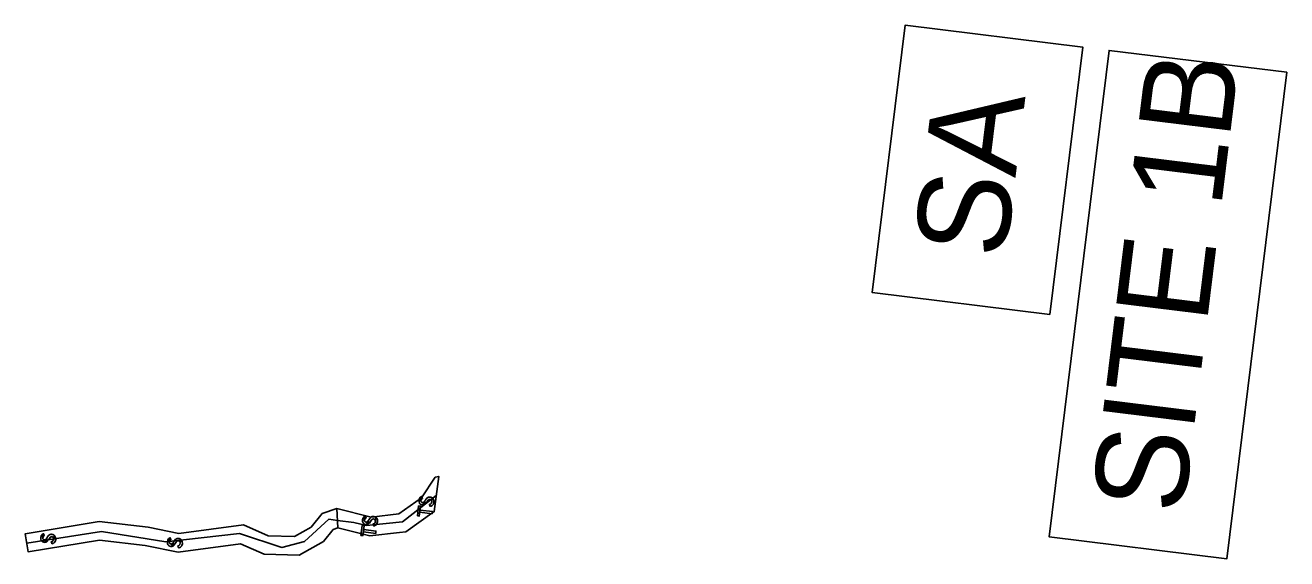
# Model space of a CAD drawing. Extents: x 474218 to 481634, y 484357 to 504997.
# Drawn here: x 481212.5 to 481417.5, y 489416.6 to 489503.2 of the extents above; entities that cross this region are included whole.
import ezdxf

# ---------------------------------------------------------------- set-up
doc = ezdxf.new("R2010")
doc.units = 0
for name, color, linetype in [('Exist Hydro Jurisdictional Stream or Body of Water', 7, 'Continuous'), ('Old_Level_29', 7, 'Continuous'), ('Prop Earthen Structure Impacts In Surface Waters Hatching CELL', 7, 'Continuous'), ('Prop Grid Mask', 7, 'Continuous'), ('Scratch_Level_4', 7, 'Continuous'), ('Temp Earthen Structure Impacts In Surface Waters Hatching CELL', 7, 'Continuous')]:
    doc.layers.add(name, color=color, linetype=linetype)

msp = doc.modelspace()

# ---------------------------------------------------------------- linework, layer by layer
at = {"layer": 'Exist Hydro Jurisdictional Stream or Body of Water'}
msp.add_lwpolyline([(481350.11, 489459.8), (481355.45, 489503.2), (481384.32, 489499.65), (481378.97, 489456.25)], close=True, dxfattribs=at)
at = {"layer": 'Old_Level_29'}
msp.add_lwpolyline([(481378.87, 489420.15), (481388.59, 489499.12), (481417.47, 489495.57), (481407.74, 489416.6)], close=True, dxfattribs=at)
at = {"layer": 'Prop Earthen Structure Impacts In Surface Waters Hatching CELL'}
msp.add_lwpolyline([(481263.15, 489424.75), (481260.77, 489423.93), (481258.97, 489421.73), (481256.27, 489420.19), (481251.99, 489420.32), (481247.94, 489422.08), (481237.44, 489420.72), (481232.46, 489421.72), (481224.51, 489422.64), (481212.5, 489420.66), (481212.99, 489417.7), (481224.59, 489419.61), (481231.98, 489418.76), (481237.33, 489417.69), (481247.5, 489419), (481251.33, 489417.34), (481257.02, 489417.17), (481260.94, 489419.4), (481262.55, 489421.37), (481263.29, 489421.62), (481263.15, 489424.75)], dxfattribs=at)
for points in [[(481215.03, 489419.78), (481215.03, 489419.75), (481215.1, 489420.33), (481215.1, 489420.32), (481215.02, 489420.04), (481215.02, 489420.04)], [(481215.64, 489419.27), (481215.73, 489419.26), (481215.78, 489419.7), (481215.69, 489419.66), (481215.56, 489419.67), (481215.55, 489419.67), (481215.52, 489419.69), (481215.44, 489419.73), (481215.42, 489419.77), (481215.38, 489419.82), (481215.37, 489419.84), (481215.37, 489419.86), (481215.36, 489419.92), (481215.35, 489420), (481215.43, 489420.64), (481215.39, 489420.63), (481215.26, 489420.54), (481215.23, 489420.52), (481215.1, 489420.33), (481215.03, 489419.75), (481215.11, 489419.57), (481215.13, 489419.52), (481215.24, 489419.42), (481215.27, 489419.39), (481215.29, 489419.37), (481215.31, 489419.36), (481215.31, 489419.35), (481215.33, 489419.35), (481215.37, 489419.33), (481215.39, 489419.32), (481215.47, 489419.29), (481215.5, 489419.28), (481215.51, 489419.27)], [(481215.51, 489420.29), (481215.6, 489420.35), (481215.54, 489420.52), (481215.52, 489420.58), (481215.49, 489420.66), (481215.47, 489420.66), (481215.46, 489420.65), (481215.45, 489420.65), (481215.43, 489420.64), (481215.35, 489420), (481215.39, 489420.16), (481215.41, 489420.18), (481215.41, 489420.19), (481215.43, 489420.21), (481215.48, 489420.27)], [(481215.88, 489419.31), (481215.93, 489419.33), (481216.01, 489419.95), (481215.94, 489419.85), (481215.83, 489419.72), (481215.78, 489419.7), (481215.73, 489419.26), (481215.77, 489419.28)], [(481217.1, 489419.92), (481217.11, 489419.77), (481217.19, 489420.42), (481217.17, 489420.44), (481217.17, 489420.44), (481217.16, 489420.45), (481217.12, 489420.48), (481217.1, 489420.49), (481217.09, 489420.49), (481217.02, 489420.52), (481216.99, 489420.53), (481216.97, 489420.53), (481216.88, 489420.56), (481216.83, 489420.56), (481216.69, 489420.57), (481216.64, 489420.57), (481216.59, 489420.55), (481216.49, 489420.51), (481216.49, 489420.51), (481216.42, 489420.48), (481216.36, 489420.42), (481216.23, 489420.29), (481216.2, 489420.25), (481216.07, 489420.05), (481216.01, 489419.95), (481215.93, 489419.33), (481215.99, 489419.37), (481216.11, 489419.47), (481216.14, 489419.51), (481216.27, 489419.68), (481216.33, 489419.77), (481216.42, 489419.91), (481216.53, 489420.07), (481216.58, 489420.11), (481216.64, 489420.16), (481216.78, 489420.18), (481216.83, 489420.17), (481216.92, 489420.15), (481216.94, 489420.13), (481216.97, 489420.12), (481217.03, 489420.07), (481217.05, 489420.05), (481217.06, 489420.02), (481217.1, 489419.94), (481217.1, 489419.93)], [(481217.36, 489419.4), (481217.45, 489419.71), (481217.44, 489420.05), (481217.44, 489420.05), (481217.33, 489420.29), (481217.31, 489420.32), (481217.19, 489420.42), (481217.11, 489419.77), (481217.06, 489419.6), (481217.06, 489419.6), (481217.05, 489419.59), (481217, 489419.5), (481216.97, 489419.47), (481216.96, 489419.46), (481216.88, 489419.41), (481216.85, 489419.39), (481216.83, 489419.38), (481216.74, 489419.36), (481216.8, 489419.16), (481216.82, 489419.11), (481216.84, 489419.04), (481216.91, 489419.06), (481216.92, 489419.06), (481216.94, 489419.06), (481216.99, 489419.07), (481217, 489419.08), (481217, 489419.08), (481217.03, 489419.09), (481217.17, 489419.17), (481217.19, 489419.18), (481217.36, 489419.4)], [(481235.6, 489419.11), (481235.61, 489419.08), (481235.68, 489419.66), (481235.67, 489419.65), (481235.6, 489419.37), (481235.6, 489419.37)], [(481236.22, 489418.6), (481236.3, 489418.59), (481236.36, 489419.03), (481236.27, 489418.99), (481236.14, 489419), (481236.13, 489419), (481236.1, 489419.01), (481236.02, 489419.06), (481235.99, 489419.09), (481235.96, 489419.15), (481235.94, 489419.17), (481235.94, 489419.19), (481235.93, 489419.25), (481235.92, 489419.33), (481236, 489419.97), (481235.96, 489419.96), (481235.83, 489419.87), (481235.8, 489419.84), (481235.68, 489419.66), (481235.61, 489419.08), (481235.69, 489418.9), (481235.71, 489418.85), (481235.81, 489418.75), (481235.85, 489418.71), (481235.87, 489418.7), (481235.88, 489418.68), (481235.88, 489418.68), (481235.9, 489418.68), (481235.94, 489418.66), (481235.97, 489418.65), (481236.05, 489418.62), (481236.08, 489418.6), (481236.09, 489418.6)], [(481236.09, 489419.62), (481236.18, 489419.68), (481236.11, 489419.85), (481236.09, 489419.91), (481236.06, 489419.99), (481236.04, 489419.98), (481236.04, 489419.98), (481236.02, 489419.98), (481236, 489419.97), (481235.92, 489419.33), (481235.96, 489419.49), (481235.98, 489419.51), (481235.99, 489419.52), (481236.01, 489419.54), (481236.05, 489419.6)], [(481236.45, 489418.64), (481236.51, 489418.66), (481236.58, 489419.28), (481236.52, 489419.17), (481236.4, 489419.05), (481236.36, 489419.03), (481236.3, 489418.59), (481236.35, 489418.6)], [(481237.68, 489419.25), (481237.68, 489419.1), (481237.76, 489419.75), (481237.74, 489419.77), (481237.74, 489419.77), (481237.73, 489419.77), (481237.69, 489419.81), (481237.67, 489419.82), (481237.66, 489419.82), (481237.59, 489419.84), (481237.56, 489419.85), (481237.54, 489419.86), (481237.46, 489419.89), (481237.4, 489419.89), (481237.27, 489419.89), (481237.21, 489419.9), (481237.16, 489419.87), (481237.07, 489419.84), (481237.07, 489419.84), (481236.99, 489419.8), (481236.94, 489419.75), (481236.81, 489419.62), (481236.78, 489419.58), (481236.64, 489419.38), (481236.58, 489419.28), (481236.51, 489418.66), (481236.56, 489418.7), (481236.68, 489418.79), (481236.71, 489418.83), (481236.85, 489419.01), (481236.9, 489419.1), (481236.99, 489419.23), (481237.1, 489419.39), (481237.15, 489419.43), (481237.22, 489419.48), (481237.35, 489419.51), (481237.41, 489419.5), (481237.5, 489419.48), (481237.52, 489419.46), (481237.54, 489419.44), (481237.61, 489419.4), (481237.62, 489419.38), (481237.63, 489419.35), (481237.67, 489419.27), (481237.68, 489419.26)], [(481237.94, 489418.73), (481238.03, 489419.04), (481238.02, 489419.38), (481238.02, 489419.38), (481237.9, 489419.62), (481237.89, 489419.65), (481237.76, 489419.75), (481237.68, 489419.1), (481237.64, 489418.93), (481237.64, 489418.92), (481237.63, 489418.91), (481237.57, 489418.83), (481237.55, 489418.8), (481237.53, 489418.79), (481237.46, 489418.74), (481237.43, 489418.72), (481237.4, 489418.71), (481237.31, 489418.69), (481237.37, 489418.49), (481237.39, 489418.44), (481237.41, 489418.37), (481237.48, 489418.39), (481237.5, 489418.39), (481237.52, 489418.39), (481237.57, 489418.4), (481237.57, 489418.41), (481237.58, 489418.41), (481237.6, 489418.42), (481237.75, 489418.5), (481237.77, 489418.51), (481237.94, 489418.72)]]:
    msp.add_lwpolyline(points, close=True, dxfattribs=at)
at = {"layer": 'Prop Grid Mask'}
for points in [[(481378.97, 489456.25), (481384.32, 489499.65), (481355.45, 489503.2), (481350.11, 489459.8)], [(481407.74, 489416.6), (481417.47, 489495.57), (481388.59, 489499.12), (481378.87, 489420.15)]]:
    msp.add_lwpolyline(points, close=True, dxfattribs=at)
at = {"layer": 'Scratch_Level_4'}
for points in [[(481276.9, 489426.48), (481279.13, 489429.82), (481279.68, 489429.96), (481278.95, 489424.26), (481274.33, 489420.98), (481273.33, 489420.87), (481268.5, 489420.31), (481263.29, 489421.62), (481263.15, 489424.75), (481268.7, 489423.35), (481273.22, 489423.87)], [(481263.29, 489421.62), (481262.55, 489421.37), (481260.94, 489419.4), (481257.02, 489417.17), (481251.33, 489417.34), (481247.5, 489419), (481237.33, 489417.69), (481231.98, 489418.76), (481224.59, 489419.61), (481212.99, 489417.7), (481212.5, 489420.66), (481224.51, 489422.64), (481232.46, 489421.72), (481237.44, 489420.72), (481247.94, 489422.08), (481251.99, 489420.32), (481256.27, 489420.19), (481258.97, 489421.73), (481260.77, 489423.93), (481263.15, 489424.75)]]:
    msp.add_lwpolyline(points, close=True, dxfattribs=at)
for points in [[(481279.28, 489426.85), (481273.82, 489422.6), (481267.97, 489421.97), (481265.9, 489422.46), (481263.23, 489422.83)], [(481263.23, 489422.83), (481261.83, 489423.03), (481257.85, 489419.38), (481254.18, 489418.44), (481247.34, 489420.72), (481235.35, 489419.37), (481224.92, 489421.02), (481212.76, 489419.12)]]:
    msp.add_lwpolyline(points, dxfattribs=at)
at = {"layer": 'Temp Earthen Structure Impacts In Surface Waters Hatching CELL'}
msp.add_line((481263.15, 489424.75), (481263.29, 489421.62), dxfattribs=at)
msp.add_lwpolyline([(481263.29, 489421.62), (481268.5, 489420.31), (481273.33, 489420.87), (481274.33, 489420.98), (481278.95, 489424.26), (481279.68, 489429.96), (481279.13, 489429.82), (481276.9, 489426.48), (481273.22, 489423.87), (481268.7, 489423.35), (481263.15, 489424.75)], dxfattribs=at)
for points in [[(481276.48, 489425.84), (481276.48, 489425.81), (481276.55, 489426.38), (481276.54, 489426.38), (481276.47, 489426.09), (481276.47, 489426.09)], [(481277.09, 489425.32), (481277.17, 489425.32), (481277.23, 489425.76), (481277.14, 489425.72), (481277.01, 489425.72), (481277, 489425.72), (481276.97, 489425.74), (481276.89, 489425.78), (481276.86, 489425.82), (481276.83, 489425.87), (481276.81, 489425.89), (481276.81, 489425.91), (481276.8, 489425.97), (481276.79, 489426.05), (481276.87, 489426.7), (481276.83, 489426.68), (481276.7, 489426.59), (481276.67, 489426.57), (481276.55, 489426.38), (481276.48, 489425.81), (481276.56, 489425.62), (481276.58, 489425.57), (481276.68, 489425.47), (481276.72, 489425.44), (481276.74, 489425.42), (481276.75, 489425.41), (481276.75, 489425.41), (481276.77, 489425.4), (481276.81, 489425.39), (481276.84, 489425.37), (481276.92, 489425.34), (481276.95, 489425.33), (481276.96, 489425.33)], [(481276.96, 489426.34), (481277.05, 489426.4), (481276.98, 489426.58), (481276.96, 489426.63), (481276.93, 489426.71), (481276.91, 489426.71), (481276.91, 489426.71), (481276.89, 489426.7), (481276.87, 489426.7), (481276.79, 489426.05), (481276.83, 489426.21), (481276.85, 489426.23), (481276.86, 489426.24), (481276.88, 489426.27), (481276.92, 489426.33)], [(481277.32, 489425.36), (481277.38, 489425.38), (481277.45, 489426), (481277.39, 489425.9), (481277.27, 489425.78), (481277.23, 489425.76), (481277.17, 489425.32), (481277.22, 489425.33)], [(481278.55, 489425.97), (481278.55, 489425.82), (481278.63, 489426.47), (481278.61, 489426.49), (481278.61, 489426.5), (481278.6, 489426.5), (481278.56, 489426.54), (481278.54, 489426.54), (481278.53, 489426.55), (481278.46, 489426.57), (481278.43, 489426.58), (481278.41, 489426.59), (481278.33, 489426.62), (481278.27, 489426.62), (481278.14, 489426.62), (481278.08, 489426.62), (481278.03, 489426.6), (481277.94, 489426.56), (481277.94, 489426.56), (481277.86, 489426.53), (481277.81, 489426.48), (481277.68, 489426.35), (481277.65, 489426.3), (481277.51, 489426.11), (481277.45, 489426), (481277.38, 489425.38), (481277.43, 489425.43), (481277.55, 489425.52), (481277.58, 489425.56), (481277.72, 489425.74), (481277.77, 489425.82), (481277.86, 489425.96), (481277.97, 489426.12), (481278.02, 489426.16), (481278.09, 489426.21), (481278.22, 489426.24), (481278.28, 489426.22), (481278.37, 489426.2), (481278.39, 489426.19), (481278.41, 489426.17), (481278.48, 489426.12), (481278.49, 489426.1), (481278.5, 489426.07), (481278.54, 489425.99), (481278.55, 489425.98)], [(481278.81, 489425.45), (481278.9, 489425.77), (481278.89, 489426.1), (481278.89, 489426.1), (481278.77, 489426.34), (481278.76, 489426.37), (481278.63, 489426.47), (481278.55, 489425.82), (481278.51, 489425.65), (481278.51, 489425.65), (481278.5, 489425.64), (481278.44, 489425.56), (481278.42, 489425.52), (481278.4, 489425.51), (481278.33, 489425.46), (481278.3, 489425.44), (481278.27, 489425.44), (481278.18, 489425.41), (481278.24, 489425.22), (481278.26, 489425.16), (481278.28, 489425.1), (481278.35, 489425.11), (481278.37, 489425.11), (481278.39, 489425.12), (481278.44, 489425.13), (481278.44, 489425.13), (481278.45, 489425.13), (481278.47, 489425.15), (481278.62, 489425.22), (481278.64, 489425.23), (481278.81, 489425.45)], [(481267.31, 489422.66), (481267.31, 489422.63), (481267.38, 489423.21), (481267.37, 489423.2), (481267.3, 489422.92), (481267.3, 489422.92)], [(481267.92, 489422.15), (481268.01, 489422.14), (481268.06, 489422.58), (481267.97, 489422.54), (481267.84, 489422.55), (481267.83, 489422.55), (481267.8, 489422.57), (481267.72, 489422.61), (481267.7, 489422.65), (481267.66, 489422.7), (481267.65, 489422.72), (481267.65, 489422.74), (481267.64, 489422.8), (481267.63, 489422.88), (481267.71, 489423.52), (481267.66, 489423.51), (481267.53, 489423.42), (481267.5, 489423.4), (481267.38, 489423.21), (481267.31, 489422.63), (481267.39, 489422.45), (481267.41, 489422.4), (481267.52, 489422.3), (481267.55, 489422.27), (481267.57, 489422.25), (481267.58, 489422.24), (481267.59, 489422.23), (481267.61, 489422.23), (481267.64, 489422.21), (481267.67, 489422.2), (481267.75, 489422.17), (481267.78, 489422.16), (481267.79, 489422.15)], [(481267.79, 489423.17), (481267.88, 489423.23), (481267.82, 489423.4), (481267.8, 489423.46), (481267.77, 489423.54), (481267.75, 489423.54), (481267.74, 489423.53), (481267.73, 489423.53), (481267.71, 489423.52), (481267.63, 489422.88), (481267.67, 489423.04), (481267.68, 489423.06), (481267.69, 489423.07), (481267.71, 489423.09), (481267.76, 489423.15)], [(481269.38, 489422.8), (481269.39, 489422.65), (481269.47, 489423.3), (481269.44, 489423.32), (481269.44, 489423.32), (481269.44, 489423.33), (481269.39, 489423.36), (481269.38, 489423.37), (481269.36, 489423.37), (481269.3, 489423.4), (481269.27, 489423.41), (481269.25, 489423.41), (481269.16, 489423.44), (481269.1, 489423.44), (481268.97, 489423.45), (481268.91, 489423.45), (481268.86, 489423.43), (481268.77, 489423.39), (481268.77, 489423.39), (481268.69, 489423.36), (481268.64, 489423.3), (481268.51, 489423.17), (481268.48, 489423.13), (481268.35, 489422.94), (481268.28, 489422.83), (481268.21, 489422.21), (481268.26, 489422.25), (481268.38, 489422.35), (481268.41, 489422.39), (481268.55, 489422.56), (481268.61, 489422.65), (481268.7, 489422.79), (481268.81, 489422.95), (481268.86, 489422.99), (481268.92, 489423.04), (481269.06, 489423.06), (481269.11, 489423.05), (481269.2, 489423.03), (481269.22, 489423.01), (481269.25, 489423), (481269.31, 489422.95), (481269.32, 489422.93), (481269.34, 489422.9), (481269.38, 489422.82), (481269.38, 489422.81)], [(481269.64, 489422.28), (481269.73, 489422.59), (481269.72, 489422.93), (481269.72, 489422.93), (481269.6, 489423.17), (481269.59, 489423.2), (481269.47, 489423.3), (481269.39, 489422.65), (481269.34, 489422.48), (481269.34, 489422.48), (481269.33, 489422.47), (481269.28, 489422.38), (481269.25, 489422.35), (481269.24, 489422.34), (481269.16, 489422.29), (481269.13, 489422.27), (481269.11, 489422.27), (481269.01, 489422.24), (481269.08, 489422.04), (481269.1, 489421.99), (481269.12, 489421.92), (481269.19, 489421.94), (481269.2, 489421.94), (481269.22, 489421.94), (481269.27, 489421.95), (481269.28, 489421.96), (481269.28, 489421.96), (481269.31, 489421.97), (481269.45, 489422.05), (481269.47, 489422.06), (481269.64, 489422.28)], [(481276.21, 489423.56), (481276.53, 489423.52), (481276.73, 489425.13), (481276.41, 489425.17)], [(481276.61, 489424.14), (481278.61, 489423.89), (481278.65, 489424.27), (481276.66, 489424.51)], [(481267.04, 489420.39), (481267.37, 489420.35), (481267.56, 489421.96), (481267.24, 489421.99)], [(481267.44, 489420.96), (481269.44, 489420.72), (481269.49, 489421.1), (481267.49, 489421.34)], [(481268.16, 489422.19), (481268.21, 489422.21), (481268.28, 489422.83), (481268.22, 489422.73), (481268.1, 489422.6), (481268.06, 489422.58), (481268.01, 489422.14), (481268.05, 489422.16)]]:
    msp.add_lwpolyline(points, close=True, dxfattribs=at)

# ---------------------------------------------------------------- texts
at = {"layer": 'Exist Hydro Jurisdictional Stream or Body of Water'}
msp.add_text('SA', height=15, rotation=82.9799, dxfattribs=at).set_placement((481371.74, 489465.08))
at = {"layer": 'Old_Level_29'}
msp.add_text('SITE 1B', height=15, rotation=82.9799, dxfattribs=at).set_placement((481400.65, 489423.62))

doc.saveas('drawing.dxf')
